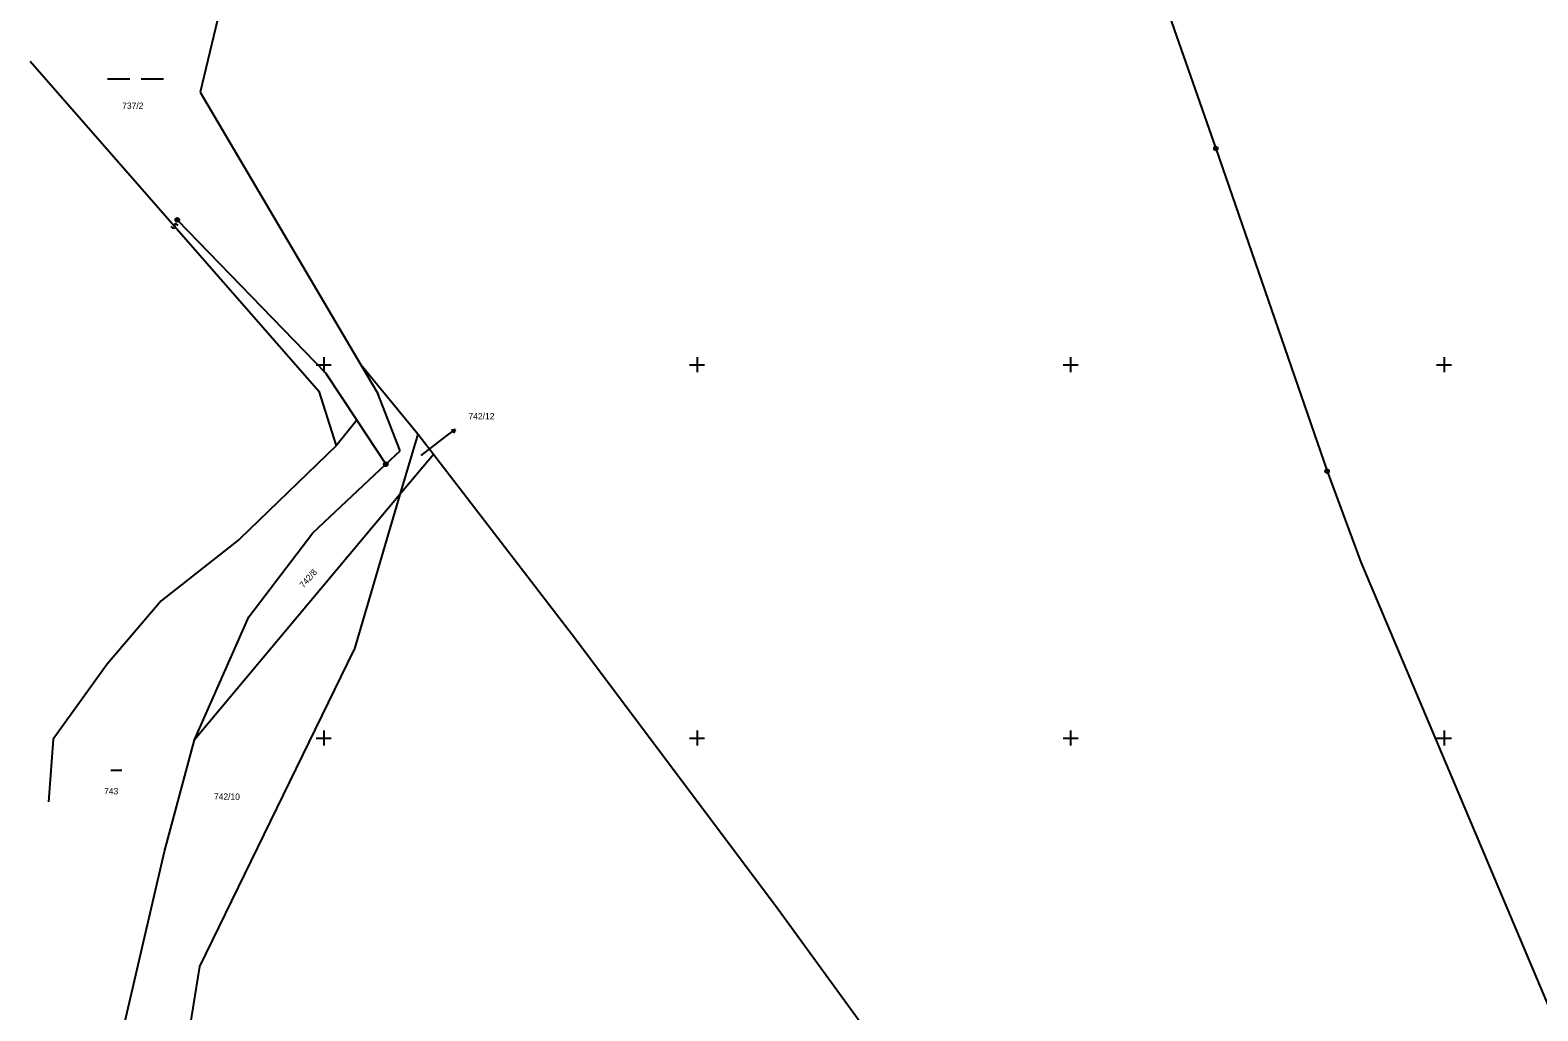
# Model space of a CAD drawing. Extents: x -493648 to -493033, y -1127718 to -1127026.
# Drawn here: x -493639.3 to -493437.4, y -1127336.5 to -1127205.2 of the extents above; entities that cross this region are included whole.
import ezdxf

# ---------------------------------------------------------------- set-up
doc = ezdxf.new("R2010")
doc.units = 0
doc.layers.add('katastrální mapa', color=7, linetype='Continuous')
doc.layers.add('síť', color=7, linetype='Continuous')

msp = doc.modelspace()

# ---------------------------------------------------------------- linework, layer by layer
at = {"layer": 'katastrální mapa'}
for p, q in [((-493494.88, -1127180.18), (-493480.54, -1127221.06)), ((-493494.88, -1127180.18), (-493480.54, -1127221.06)), ((-493612.5, -1127196.61), (-493616.55, -1127213.51)), ((-493639.3, -1127209.34), (-493600.63, -1127253.53)), ((-493628.94, -1127211.72), (-493625.94, -1127211.72)), ((-493624.44, -1127211.72), (-493621.44, -1127211.72)), ((-493616.55, -1127213.51), (-493595.03, -1127250.02)), ((-493480.54, -1127221.06), (-493465.65, -1127264.27)), ((-493480.54, -1127221.06), (-493465.65, -1127264.27)), ((-493620.16, -1127231.74), (-493620.43, -1127231.51)), ((-493620.02, -1127231.75), (-493620.16, -1127231.74)), ((-493619.95, -1127231.68), (-493620.02, -1127231.75)), ((-493619.98, -1127231.19), (-493619.99, -1127231.33)), ((-493619.99, -1127231.33), (-493619.94, -1127231.54)), ((-493619.91, -1127231.12), (-493619.98, -1127231.19)), ((-493619.94, -1127231.54), (-493619.95, -1127231.68)), ((-493619.77, -1127231.13), (-493619.91, -1127231.12)), ((-493619.5, -1127231.36), (-493619.77, -1127231.13)), ((-493619.6, -1127230.6), (-493599.75, -1127251.1)), ((-493595.03, -1127250.02), (-493592.77, -1127253.87)), ((-493587.41, -1127259.3), (-493595.03, -1127250.02)), ((-493599.75, -1127251.1), (-493595.58, -1127257.42)), ((-493600.63, -1127253.53), (-493598.32, -1127260.88)), ((-493589.75, -1127261.52), (-493592.77, -1127253.87)), ((-493595.58, -1127257.42), (-493598.32, -1127260.88)), ((-493595.58, -1127257.42), (-493591.68, -1127263.34)), ((-493587.41, -1127259.3), (-493589.79, -1127267.39)), ((-493585.3, -1127262.04), (-493587.41, -1127259.3)), ((-493586.96, -1127262.15), (-493583.59, -1127259.59)), ((-493583.59, -1127259.59), (-493582.4, -1127258.68)), ((-493582.4, -1127258.68), (-493582.95, -1127258.79)), ((-493582.4, -1127258.68), (-493582.64, -1127259.18)), ((-493598.32, -1127260.88), (-493611.28, -1127273.37)), ((-493591.68, -1127263.34), (-493589.75, -1127261.52)), ((-493585.3, -1127262.04), (-493589.79, -1127267.39)), ((-493566.73, -1127286.17), (-493585.3, -1127262.04)), ((-493601.43, -1127272.51), (-493591.68, -1127263.34)), ((-493465.65, -1127264.27), (-493461.12, -1127276.43)), ((-493465.65, -1127264.27), (-493461.12, -1127276.43)), ((-493589.79, -1127267.39), (-493617.31, -1127300.23)), ((-493589.79, -1127267.39), (-493595.91, -1127288.18)), ((-493610, -1127283.75), (-493601.43, -1127272.51)), ((-493611.28, -1127273.37), (-493621.77, -1127281.63)), ((-493461.12, -1127276.43), (-493435.88, -1127336.26)), ((-493621.77, -1127281.63), (-493628.98, -1127290.11)), ((-493617.31, -1127300.23), (-493610, -1127283.75)), ((-493539.49, -1127322.46), (-493566.73, -1127286.17)), ((-493616.6, -1127330.59), (-493595.91, -1127288.18)), ((-493628.98, -1127290.11), (-493636.21, -1127300.12)), ((-493636.21, -1127300.12), (-493636.84, -1127308.53)), ((-493621.33, -1127315.16), (-493617.31, -1127300.23)), ((-493628.51, -1127304.3), (-493627.01, -1127304.3)), ((-493628.01, -1127344.09), (-493621.33, -1127315.16)), ((-493491.36, -1127388.6), (-493539.49, -1127322.46)), ((-493619.14, -1127346.56), (-493616.6, -1127330.59))]:
    msp.add_line(p, q, dxfattribs=at)
for centre, radius in [((-493480.54, -1127221.06), 0.25), ((-493480.54, -1127221.06), 0.005), ((-493619.6, -1127230.6), 0.25), ((-493619.6, -1127230.6), 0.005), ((-493591.68, -1127263.34), 0.25), ((-493591.68, -1127263.34), 0.005), ((-493465.65, -1127264.27), 0.25), ((-493465.65, -1127264.27), 0.005)]:
    msp.add_circle(centre, radius, dxfattribs=at)
at = {"layer": 'síť'}
for p, q in [((-493601, -1127250), (-493599, -1127250)), ((-493600, -1127249), (-493600, -1127251)), ((-493551, -1127250), (-493549, -1127250)), ((-493550, -1127249), (-493550, -1127251)), ((-493501, -1127250), (-493499, -1127250)), ((-493500, -1127249), (-493500, -1127251)), ((-493451, -1127250), (-493449, -1127250)), ((-493450, -1127249), (-493450, -1127251)), ((-493601, -1127300), (-493599, -1127300)), ((-493600, -1127299), (-493600, -1127301)), ((-493551, -1127300), (-493549, -1127300)), ((-493550, -1127299), (-493550, -1127301)), ((-493501, -1127300), (-493499, -1127300)), ((-493500, -1127299), (-493500, -1127301)), ((-493451, -1127300), (-493449, -1127300)), ((-493450, -1127299), (-493450, -1127301))]:
    msp.add_line(p, q, dxfattribs=at)

# ---------------------------------------------------------------- texts
at = {"layer": 'katastrální mapa'}
for s, height, p in [('737/2', 0.849996, (-493626.98, -1127215.75)), ('742/12', 0.849996, (-493580.61, -1127257.32)), ('742/12', 0.049998, (-493586.96, -1127262.15)), ('743', 0.849996, (-493629.4, -1127307.53)), ('742/10', 0.849996, (-493614.69, -1127308.26))]:
    msp.add_text(s, height=height, dxfattribs=at).set_placement(p)
msp.add_text('742/8', height=0.849996, rotation=48.5999972, dxfattribs=at).set_placement((-493602.69, -1127279.97))

doc.saveas('drawing.dxf')
